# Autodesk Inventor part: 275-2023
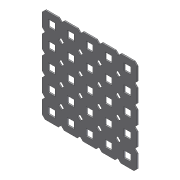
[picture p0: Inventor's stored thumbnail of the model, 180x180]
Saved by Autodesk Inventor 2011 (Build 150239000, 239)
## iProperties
Company: Autodesk Inc.
Created: 2005-08
Part Number: 275-2023
Document SubType Name: Sheet Metal
Designer: Autodesk Inc.
Density: 1 g/cm^3
Sheet Metal Rule: Default
Catalog Web Link: http://www.vexrobotics.com/products/accessories/structure/plate.html
Description: Plate with holes on 0.500" increments and 1/8" diamonds in between. Can be cut on 0.500" increments.
Vendor: Innovation First, Inc.
Author: Autodesk Inc.
Title: VEX Robotics Kit of Parts
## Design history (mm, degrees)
node "Face1"
  sketch "Sketch1"
    geometry: L1 (-15.07, 9.738)-(-23.96, 9.738); L2 (-25.865, 7.833)-(-25.865, -1.057); L3 (-23.96, -2.962)-(-15.07, -2.962); L4 (-13.165, -1.057)-(-13.165, 7.833); L5 (-25.865, 7.833)-(-23.96, 9.738); L6 (-25.865, -1.057)-(-23.96, -2.962); L7 (-15.07, -2.962)-(-13.165, -1.057); L8 (-13.165, 7.833)-(-15.07, 9.738); L9 (-21.801, 5.674)-(-17.229, 5.674); L10 (-17.229, 5.674)-(-17.229, 1.102); L11 (-17.229, 1.102)-(-21.801, 1.102); L12 (-21.801, 1.102)-(-21.801, 5.674); 4 further points
    constraints: 24 end point, 8 point on line, 4 parallel, 2 horizontal, 2 perpendicular
    dimensions: "d0" = 12.7 distance of point (-25.865, 9.738) point (-25.865, -2.962); "d1" = 12.7 distance of point (-13.165, 9.738) point (-25.865, 9.738); "d2" = 1.905 distance of L2.start point (-25.865, 9.738); "d3" = 1.905 distance of L1.end point (-25.865, 9.738) (= d2); "d4" = 1.905 distance of L2.end point (-25.865, -2.962) (= d2); "d5" = 1.905 distance of L3.start point (-25.865, -2.962) (= d4); "d6" = 1.905 distance of L3.end point (-13.165, -2.962) (= d2); "d7" = 1.905 distance of L4.start point (-13.165, -2.962) (= d6); "d8" = 1.905 distance of L4.end point (-13.165, 9.738) (= d2); "d9" = 1.905 distance of L1.start point (-13.165, 9.738) (= d8); "d10" = 4.572 distance of L11.end L9.start; "d11" = 4.572 distance of L10.end L11.end; "d12" = 4.064 distance between parallel lines of L1 L9; "d13" = 4.064 distance between parallel lines of L4 L10
body "Solid1"
pattern_linear "Rectangular Pattern1" dims "d17" = 12.7, "d23" = 12.7
face "Plate1" dims "Thickness" = 0.8509
other parameters: "BendRadius" = 0.8509 (= Thickness), "BendReliefWidth" = 0.8509 (= Thickness), "BendReliefDepth" = 0.42545 (= 0.5 x Thickness), "CornerReliefSize" = 3.4036 (= 4 x Thickness), "SeamGap" = 0.00508, "MinimumRemnant" = 1.7018 (= 2 x Thickness), "TransitionRadius" = 0.8509 (= BendRadius), "d14" = 0.8509 (= BendRadius), "JacobiRadiusSize" = 0.8509 (= Thickness), "GapSize" = 0.8509 (= Thickness)
